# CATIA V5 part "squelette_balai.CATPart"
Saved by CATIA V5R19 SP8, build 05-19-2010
Part number: squelette_balai
Publications: "Plan.1", "Plan.3", "Droite.1", "Plan.5"
Bounding box of the stored display mesh (mm): x -2.149 to 43.851, y 203.618 to 321.582, z 69.986 to 101.109
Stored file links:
  G:\EU_thinkMotion\CFAO_2010\MMS_groupe3\MMS_groupe3\A reprendre\amenand\amenand\squelette_balai.CATPart
  F:\thinkmotion CFAO v12.1\essuie_glace.CATProduct
  G:\EU_thinkMotion\CFAO_2010\MMS_groupe3\MMS_groupe3\A reprendre\amenand\amenand\pignon.CATPart
  G:\EU_thinkMotion\CFAO_2010\MMS_groupe3\MMS_groupe3\A reprendre\amenand\amenand\coulisseau.CATPart
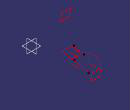
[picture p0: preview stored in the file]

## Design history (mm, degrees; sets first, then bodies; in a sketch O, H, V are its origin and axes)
Set1
  Plane1: linked copy from another document
  Plane2: linked copy from another document
  Point1: linked copy from another document
  Line1: linked copy from another document
Set2 "set géométrique.12"
  Plane3: type Offset, RefPlane Plane1, Offset 46, reversed
  Plane4: type Offset, RefPlane Plane2, Offset 210
  Point2: type OnPlane, Support Plane3, RefPoint Point1, H 0, V 0, Direction (0, 1, 0)
  Line2: type PtDir, RefPoint Point2, Direction Line1, Support Plane3, Start 0, End 50
  Plane5: type Angle, RefPlane Plane3, Direction Line2, Angle 90
Body1 (main body)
